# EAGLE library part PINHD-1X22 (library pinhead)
PIN HEADER
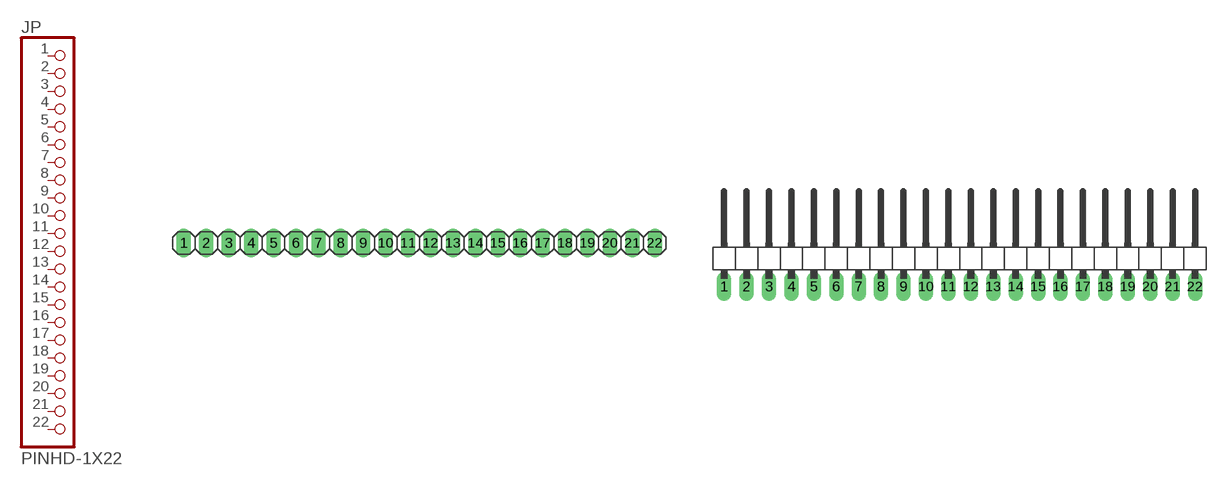
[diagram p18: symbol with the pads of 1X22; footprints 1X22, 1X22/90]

Designator prefix JP

## PINHD-1X22  [1X22]
1  1  pas
2  2  pas
3  3  pas
4  4  pas
5  5  pas
6  6  pas
7  7  pas
8  8  pas
9  9  pas
10  10  pas
11  11  pas
12  12  pas
13  13  pas
14  14  pas
15  15  pas
16  16  pas
17  17  pas
18  18  pas
19  19  pas
20  20  pas
21  21  pas
22  22  pas

## PINHD-1X22/90  [1X22/90]
Pads as for 1X22

## Footprint 1X22 (pad centres in mm)
PIN HEADER
drill 1.016 pad 1.67 long: 1 -26.67,0; 2 -24.13,0; 3 -21.59,0; 4 -19.05,0; 5 -16.51,0; 6 -13.97,0; 7 -11.43,0; 8 -8.89,0; 9 -6.35,0; 10 -3.81,0; 11 -1.27,0; 12 1.27,0; 13 3.81,0; 14 6.35,0; 15 8.89,0; 16 11.43,0; 17 13.97,0; 18 16.51,0; 19 19.05,0; 20 21.59,0; 21 24.13,0; 22 26.67,0

## Footprint 1X22/90 (pad centres in mm)
PIN HEADER
drill 1.016 pad 1.67 long: 1 -26.67,-3.81; 2 -24.13,-3.81; 3 -21.59,-3.81; 4 -19.05,-3.81; 5 -16.51,-3.81; 6 -13.97,-3.81; 7 -11.43,-3.81; 8 -8.89,-3.81; 9 -6.35,-3.81; 10 -3.81,-3.81; 11 -1.27,-3.81; 12 1.27,-3.81; 13 3.81,-3.81; 14 6.35,-3.81; 15 8.89,-3.81; 16 11.43,-3.81; 17 13.97,-3.81; 18 16.51,-3.81; 19 19.05,-3.81; 20 21.59,-3.81; 21 24.13,-3.81; 22 26.67,-3.81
